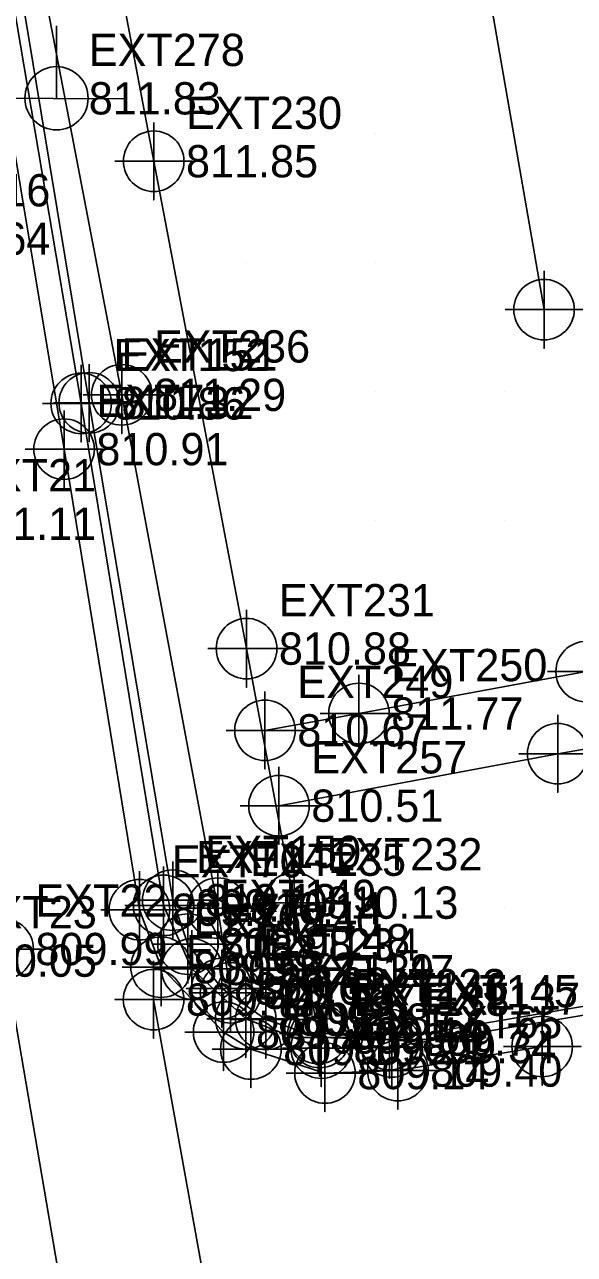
# Model space of a CAD drawing. Extents: x 1762120 to 1766775, y 709485 to 712965.
# Drawn here: x 1763832.9 to 1763875.4, y 712653.2 to 712748.4 of the extents above; entities that cross this region are included whole.
import ezdxf

# ---------------------------------------------------------------- set-up
doc = ezdxf.new("R2010")
doc.units = 0
for name, color, linetype in [('Exist Building', 7, 'Continuous'), ('Exist Building Cogo Point CELL', 7, 'Continuous'), ('Exist DTM Crownline Cogo Elevation', 7, 'Continuous'), ('Exist DTM Crownline Cogo Number', 7, 'Continuous'), ('Exist DTM Drainline', 7, 'Continuous'), ('Exist DTM Drainline Cogo Elevation', 7, 'Continuous'), ('Exist DTM Drainline Cogo Number', 7, 'Continuous'), ('Exist DTM Drainline Cogo Point CELL', 7, 'Continuous'), ('Exist DTM QL2 LIDAR Elevation Point', 7, 'Continuous'), ('Exist Roads Curbs', 7, 'Continuous'), ('Exist Roads Curbs Cogo Elevation', 7, 'Continuous'), ('Exist Roads Curbs Cogo Number', 7, 'Continuous'), ('Exist Roads Curbs Cogo Point CELL', 7, 'Continuous'), ('Exist Roads EOP', 7, 'Continuous'), ('Exist Roads EOP Cogo Elevation', 7, 'Continuous'), ('Exist Roads EOP Cogo Number', 7, 'Continuous'), ('Exist Roads EOP Cogo Point CELL', 7, 'Continuous'), ('Exist Roads EOP Other', 7, 'Continuous'), ('Exist Roads EOP Other Cogo Elevation', 7, 'Continuous'), ('Exist Roads EOP Other Cogo Number', 7, 'Continuous'), ('Exist Roads EOP Other Cogo Point CELL', 7, 'Continuous'), ('Exist Roads EOT', 7, 'Continuous'), ('Exist Roads EOT Cogo Elevation', 7, 'Continuous'), ('Exist Roads EOT Cogo Number', 7, 'Continuous'), ('Exist Roads EOT Cogo Point CELL', 7, 'Continuous'), ('Exist Utilities Power Joint Use Telephone CELL', 7, 'Continuous'), ('Exist Utilities Power Joint Use Telephone Cogo Elevation', 7, 'Continuous'), ('Exist Utilities Power Joint Use Telephone Cogo Number', 7, 'Continuous')]:
    doc.layers.add(name, color=color, linetype=linetype)

msp = doc.modelspace()

# ---------------------------------------------------------------- linework, layer by layer
at = {"layer": 'Exist Building'}
msp.add_line((1763873.081, 712726.353), (1763860.691, 712797.906), dxfattribs=at)
at = {"layer": 'Exist Building Cogo Point CELL'}
msp.add_lwpolyline([(1763873.081, 712729.353), (1763873.081, 712723.353), (1763873.081, 712726.353), (1763876.081, 712726.353), (1763870.081, 712726.353)], dxfattribs=at)
msp.add_circle((1763873.081, 712726.353), 2.344, dxfattribs=at)
at = {"layer": 'Exist DTM Drainline'}
msp.add_lwpolyline([(1763888.176, 712675.965), (1763883.465, 712673.426), (1763879.421, 712672.239), (1763861.295, 712669.219), (1763855.834, 712669.139), (1763849.992, 712671.404), (1763845.815, 712675.27), (1763843.641, 712680.197), (1763837.254, 712719.085), (1763830.877, 712756.626), (1763824.422, 712795.511), (1763818.53, 712833.611)], dxfattribs=at)
at = {"layer": 'Exist DTM Drainline Cogo Point CELL'}
for points in [[(1763837.254, 712722.085), (1763837.254, 712716.085), (1763837.254, 712719.085), (1763840.254, 712719.085), (1763834.254, 712719.085)], [(1763843.641, 712683.197), (1763843.641, 712677.197), (1763843.641, 712680.197), (1763846.641, 712680.197), (1763840.641, 712680.197)], [(1763845.815, 712678.27), (1763845.815, 712672.27), (1763845.815, 712675.27), (1763848.815, 712675.27), (1763842.815, 712675.27)], [(1763849.992, 712674.404), (1763849.992, 712668.404), (1763849.992, 712671.404), (1763852.992, 712671.404), (1763846.992, 712671.404)], [(1763855.834, 712672.139), (1763855.834, 712666.139), (1763855.834, 712669.139), (1763858.834, 712669.139), (1763852.834, 712669.139)], [(1763861.295, 712672.219), (1763861.295, 712666.219), (1763861.295, 712669.219), (1763864.295, 712669.219), (1763858.295, 712669.219)]]:
    msp.add_lwpolyline(points, dxfattribs=at)
for centre in [(1763837.254, 712719.085), (1763843.641, 712680.197), (1763845.815, 712675.27), (1763849.992, 712671.404), (1763861.295, 712669.219), (1763855.834, 712669.139)]:
    msp.add_circle(centre, 2.344, dxfattribs=at)
at = {"layer": 'Exist DTM QL2 LIDAR Elevation Point'}
for p, q in [((1763850, 712740), (1763850, 712740)), ((1763860, 712740), (1763860, 712740)), ((1763850, 712730), (1763850, 712730)), ((1763860, 712730), (1763860, 712730)), ((1763850, 712720), (1763850, 712720)), ((1763860, 712720), (1763860, 712720)), ((1763870, 712720), (1763870, 712720)), ((1763860, 712710), (1763860, 712710)), ((1763870, 712710), (1763870, 712710)), ((1763860, 712700), (1763860, 712700)), ((1763870, 712700), (1763870, 712700)), ((1763860, 712680), (1763860, 712680)), ((1763870, 712680), (1763870, 712680))]:
    msp.add_line(p, q, dxfattribs=at)
at = {"layer": 'Exist Roads Curbs'}
msp.add_lwpolyline([(1763887.913, 712676.609), (1763883.105, 712673.993), (1763879.529, 712672.953), (1763861.13, 712669.797), (1763855.716, 712669.958), (1763851.546, 712671.351), (1763848.135, 712673.751), (1763845.524, 712677.19), (1763844.339, 712680.601), (1763837.881, 712719.135), (1763831.693, 712756.599), (1763825.169, 712795.603), (1763818.676, 712837.176), (1763818.589, 712840.745), (1763820.694, 712846.562), (1763822.71, 712849.767), (1763826.551, 712853.145), (1763830.571, 712855.107), (1763844.339, 712857.64), (1763850.134, 712857.271), (1763855.594, 712854.564), (1763859.316, 712849.842), (1763861.632, 712843.383)], dxfattribs=at)
at = {"layer": 'Exist Roads Curbs Cogo Point CELL'}
for points in [[(1763837.881, 712722.135), (1763837.881, 712716.135), (1763837.881, 712719.135), (1763835.151, 712719.135), (1763840.881, 712719.135)], [(1763844.339, 712683.601), (1763844.339, 712677.601), (1763844.339, 712680.601), (1763841.609, 712680.601), (1763847.339, 712680.601)], [(1763845.524, 712680.19), (1763845.524, 712674.19), (1763845.524, 712677.19), (1763842.794, 712677.19), (1763848.524, 712677.19)], [(1763848.135, 712676.751), (1763848.135, 712670.751), (1763848.135, 712673.751), (1763845.405, 712673.751), (1763851.135, 712673.751)], [(1763851.546, 712674.351), (1763851.546, 712668.351), (1763851.546, 712671.351), (1763848.816, 712671.351), (1763854.546, 712671.351)], [(1763855.716, 712672.958), (1763855.716, 712666.958), (1763855.716, 712669.958), (1763852.986, 712669.958), (1763858.716, 712669.958)], [(1763861.13, 712672.797), (1763861.13, 712666.797), (1763861.13, 712669.797), (1763858.4, 712669.797), (1763864.13, 712669.797)]]:
    msp.add_lwpolyline(points, dxfattribs=at)
for centre in [(1763837.881, 712719.135), (1763844.339, 712680.601), (1763845.524, 712677.19), (1763848.135, 712673.751), (1763851.546, 712671.351), (1763855.716, 712669.958), (1763861.13, 712669.797)]:
    msp.add_circle(centre, 2.344, dxfattribs=at)
at = {"layer": 'Exist Roads EOP'}
msp.add_lwpolyline([(1763872.939, 712669.264), (1763861.771, 712667.397), (1763856.129, 712667.205), (1763850.394, 712669.068), (1763848.283, 712670.385), (1763843.436, 712675.406), (1763841.767, 712679.86), (1763835.931, 712715.544), (1763829.184, 712756.072), (1763822.427, 712796.443), (1763817.324, 712826.974), (1763816.07, 712838.811), (1763818.954, 712848.93), (1763823.982, 712854.424), (1763830.822, 712857.794), (1763839.256, 712859.239)], dxfattribs=at)
at = {"layer": 'Exist Roads EOP Cogo Point CELL'}
for points in [[(1763835.931, 712718.544), (1763835.931, 712712.544), (1763835.931, 712715.544), (1763838.931, 712715.544), (1763832.931, 712715.544)], [(1763841.767, 712682.86), (1763841.767, 712676.86), (1763841.767, 712679.86), (1763844.767, 712679.86), (1763838.767, 712679.86)], [(1763843.436, 712678.406), (1763843.436, 712672.406), (1763843.436, 712675.406), (1763846.436, 712675.406), (1763840.436, 712675.406)], [(1763848.283, 712673.385), (1763848.283, 712667.385), (1763848.283, 712670.385), (1763851.283, 712670.385), (1763845.283, 712670.385)], [(1763850.394, 712672.068), (1763850.394, 712666.068), (1763850.394, 712669.068), (1763853.394, 712669.068), (1763847.394, 712669.068)], [(1763872.939, 712672.264), (1763872.939, 712666.264), (1763872.939, 712669.264), (1763875.939, 712669.264), (1763869.939, 712669.264)], [(1763856.129, 712670.205), (1763856.129, 712664.205), (1763856.129, 712667.205), (1763859.129, 712667.205), (1763853.129, 712667.205)], [(1763861.771, 712670.397), (1763861.771, 712664.397), (1763861.771, 712667.397), (1763864.771, 712667.397), (1763858.771, 712667.397)]]:
    msp.add_lwpolyline(points, dxfattribs=at)
for centre in [(1763835.931, 712715.544), (1763841.767, 712679.86), (1763843.436, 712675.406), (1763848.283, 712670.385), (1763872.939, 712669.264), (1763850.394, 712669.068), (1763861.771, 712667.397), (1763856.129, 712667.205)]:
    msp.add_circle(centre, 2.344, dxfattribs=at)
at = {"layer": 'Exist Roads EOP Other'}
for points in [[(1763823.74, 712850.658), (1763829.272, 712813.477), (1763835.791, 712775.327), (1763842.869, 712737.848), (1763850.058, 712700.088), (1763853.731, 712680.407), (1763855.596, 712670.266)], [(1763848.821, 712673.422), (1763847.825, 712679.985), (1763840.398, 712719.751), (1763833.777, 712754.373), (1763826.475, 712793.95), (1763821.461, 712826.921), (1763819.116, 712842.201)], [(1763851.484, 712693.757), (1763858.758, 712695.065), (1763876.347, 712698.307), (1763886.241, 712700.113), (1763914.739, 712705.328)], [(1763916.286, 712699.606), (1763891.551, 712695.001), (1763874.144, 712691.949), (1763852.567, 712687.92)]]:
    msp.add_lwpolyline(points, dxfattribs=at)
at = {"layer": 'Exist Roads EOP Other Cogo Point CELL'}
for points in [[(1763842.869, 712740.848), (1763842.869, 712734.848), (1763842.869, 712737.848), (1763845.869, 712737.848), (1763839.869, 712737.848)], [(1763840.398, 712722.751), (1763840.398, 712716.751), (1763840.398, 712719.751), (1763843.398, 712719.751), (1763837.398, 712719.751)], [(1763850.058, 712703.088), (1763850.058, 712697.088), (1763850.058, 712700.088), (1763853.058, 712700.088), (1763847.058, 712700.088)], [(1763876.347, 712701.307), (1763876.347, 712695.307), (1763876.347, 712698.307), (1763879.347, 712698.307), (1763873.347, 712698.307)], [(1763858.758, 712698.065), (1763858.758, 712692.065), (1763858.758, 712695.065), (1763861.758, 712695.065), (1763855.758, 712695.065)], [(1763851.484, 712696.757), (1763851.484, 712690.757), (1763851.484, 712693.757), (1763854.484, 712693.757), (1763848.484, 712693.757)], [(1763874.144, 712694.949), (1763874.144, 712688.949), (1763874.144, 712691.949), (1763877.144, 712691.949), (1763871.144, 712691.949)], [(1763852.567, 712690.92), (1763852.567, 712684.92), (1763852.567, 712687.92), (1763855.567, 712687.92), (1763849.567, 712687.92)], [(1763847.825, 712682.985), (1763847.825, 712676.985), (1763847.825, 712679.985), (1763850.825, 712679.985), (1763844.825, 712679.985)], [(1763853.731, 712683.407), (1763853.731, 712677.407), (1763853.731, 712680.407), (1763856.731, 712680.407), (1763850.731, 712680.407)], [(1763848.821, 712676.422), (1763848.821, 712670.422), (1763848.821, 712673.422), (1763851.821, 712673.422), (1763845.821, 712673.422)], [(1763855.596, 712673.266), (1763855.596, 712667.266), (1763855.596, 712670.266), (1763858.596, 712670.266), (1763852.596, 712670.266)]]:
    msp.add_lwpolyline(points, dxfattribs=at)
for centre in [(1763842.869, 712737.848), (1763840.398, 712719.751), (1763850.058, 712700.088), (1763876.347, 712698.307), (1763858.758, 712695.065), (1763851.484, 712693.757), (1763874.144, 712691.949), (1763852.567, 712687.92), (1763847.825, 712679.985), (1763853.731, 712680.407), (1763848.821, 712673.422), (1763855.596, 712670.266)]:
    msp.add_circle(centre, 2.344, dxfattribs=at)
at = {"layer": 'Exist Roads EOT'}
msp.add_line((1763842.863, 712672.898), (1763849.88, 712633.986), dxfattribs=at)
msp.add_lwpolyline([(1763789.832, 712926.884), (1763795.992, 712888.052), (1763800.75, 712859.942), (1763807.254, 712820.955), (1763816.86, 712762.721), (1763822.148, 712731.849), (1763825.695, 712709.767), (1763831.213, 712676.817), (1763837.744, 712638.56), (1763842.2, 712611.183), (1763849.139, 712569.759)], dxfattribs=at)
at = {"layer": 'Exist Roads EOT Cogo Point CELL'}
for points in [[(1763831.213, 712679.817), (1763831.213, 712673.817), (1763831.213, 712676.817), (1763828.213, 712676.817), (1763834.213, 712676.817)], [(1763842.863, 712675.898), (1763842.863, 712669.898), (1763842.863, 712672.898), (1763839.863, 712672.898), (1763845.863, 712672.898)]]:
    msp.add_lwpolyline(points, dxfattribs=at)
for centre in [(1763831.213, 712676.817), (1763842.863, 712672.898)]:
    msp.add_circle(centre, 2.344, dxfattribs=at)
at = {"layer": 'Exist Utilities Power Joint Use Telephone CELL'}
msp.add_line((1763835.346, 712742.723), (1763835.346, 712742.723), dxfattribs=at)
msp.add_lwpolyline([(1763829.409, 712742.723), (1763840.746, 712742.685), (1763835.346, 712742.703), (1763835.346, 712748.348)], dxfattribs=at)
msp.add_circle((1763835.347, 712742.729), 2.45, dxfattribs=at)

# ---------------------------------------------------------------- texts
at = {"layer": 'Exist DTM Crownline Cogo Elevation'}
msp.add_text('810.05', height=2.5, dxfattribs=at).set_placement((1763828.249, 712674.666))
at = {"layer": 'Exist DTM Crownline Cogo Number'}
msp.add_text('EXT23', height=2.5, dxfattribs=at).set_placement((1763828.249, 712678.416))
at = {"layer": 'Exist DTM Drainline Cogo Elevation'}
for s, p in [('810.86', (1763839.754, 712717.835)), ('809.70', (1763846.141, 712678.947)), ('809.52', (1763848.315, 712674.02)), ('809.28', (1763852.492, 712670.154)), ('809.21', (1763858.334, 712667.889)), ('809.34', (1763863.795, 712667.969))]:
    msp.add_text(s, height=2.5, dxfattribs=at).set_placement(p)
at = {"layer": 'Exist DTM Drainline Cogo Number'}
for s, p in [('EXT152', (1763839.754, 712721.585)), ('EXT141', (1763846.141, 712682.697)), ('EXT140', (1763848.315, 712677.77)), ('EXT139', (1763852.492, 712673.904)), ('EXT138', (1763858.334, 712671.639)), ('EXT137', (1763863.795, 712671.719))]:
    msp.add_text(s, height=2.5, dxfattribs=at).set_placement(p)
at = {"layer": 'Exist Roads Curbs Cogo Elevation'}
for s, p in [('811.32', (1763840.381, 712717.885)), ('810.13', (1763846.839, 712679.351)), ('809.98', (1763848.024, 712675.94)), ('809.62', (1763850.635, 712672.501)), ('809.38', (1763854.046, 712670.101)), ('809.50', (1763858.216, 712668.708)), ('809.72', (1763863.63, 712668.547))]:
    msp.add_text(s, height=2.5, dxfattribs=at).set_placement(p)
at = {"layer": 'Exist Roads Curbs Cogo Number'}
for s, p in [('EXT151', (1763840.381, 712721.635)), ('EXT150', (1763846.839, 712683.101)), ('EXT149', (1763848.024, 712679.69)), ('EXT148', (1763850.635, 712676.251)), ('EXT147', (1763854.046, 712673.851)), ('EXT146', (1763858.216, 712672.458)), ('EXT145', (1763863.63, 712672.297))]:
    msp.add_text(s, height=2.5, dxfattribs=at).set_placement(p)
at = {"layer": 'Exist Roads EOP Cogo Elevation'}
for s, p in [('810.91', (1763838.431, 712714.294)), ('809.77', (1763844.267, 712678.61)), ('809.52', (1763845.936, 712674.156)), ('809.20', (1763850.783, 712669.135)), ('809.16', (1763852.894, 712667.818)), ('809.40', (1763864.271, 712666.147)), ('809.14', (1763858.629, 712665.955))]:
    msp.add_text(s, height=2.5, dxfattribs=at).set_placement(p)
at = {"layer": 'Exist Roads EOP Cogo Number'}
for s, p in [('EXT71', (1763838.431, 712718.044)), ('EXT70', (1763844.267, 712682.36)), ('EXT69', (1763845.936, 712677.906)), ('EXT68', (1763850.783, 712672.885)), ('EXT67', (1763852.894, 712671.568)), ('EXT66', (1763858.629, 712669.705)), ('EXT65', (1763864.271, 712669.897))]:
    msp.add_text(s, height=2.5, dxfattribs=at).set_placement(p)
at = {"layer": 'Exist Roads EOP Other Cogo Elevation'}
for s, p in [('811.85', (1763845.369, 712736.598)), ('811.29', (1763842.898, 712718.501)), ('810.88', (1763852.558, 712698.838)), ('811.77', (1763861.258, 712693.815)), ('810.67', (1763853.984, 712692.507)), ('810.51', (1763855.067, 712686.67)), ('810.14', (1763850.325, 712678.735)), ('810.13', (1763856.231, 712679.157)), ('809.58', (1763851.321, 712672.172)), ('809.44', (1763858.096, 712669.016))]:
    msp.add_text(s, height=2.5, dxfattribs=at).set_placement(p)
at = {"layer": 'Exist Roads EOP Other Cogo Number'}
for s, p in [('EXT230', (1763845.369, 712740.348)), ('EXT236', (1763842.898, 712722.251)), ('EXT231', (1763852.558, 712702.588)), ('EXT250', (1763861.258, 712697.565)), ('EXT249', (1763853.984, 712696.257)), ('EXT257', (1763855.067, 712690.42)), ('EXT235', (1763850.325, 712682.485)), ('EXT232', (1763856.231, 712682.907)), ('EXT234', (1763851.321, 712675.922)), ('EXT233', (1763858.096, 712672.766))]:
    msp.add_text(s, height=2.5, dxfattribs=at).set_placement(p)
at = {"layer": 'Exist Roads EOT Cogo Elevation'}
for s, p in [('811.64', (1763824.648, 712730.599)), ('811.11', (1763828.195, 712708.517)), ('809.99', (1763833.713, 712675.567)), ('809.44', (1763845.363, 712671.648))]:
    msp.add_text(s, height=2.5, dxfattribs=at).set_placement(p)
at = {"layer": 'Exist Roads EOT Cogo Number'}
for s, p in [('EXT16', (1763824.648, 712734.349)), ('EXT21', (1763828.195, 712712.267)), ('EXT22', (1763833.713, 712679.317)), ('EXT63', (1763845.363, 712675.398))]:
    msp.add_text(s, height=2.5, dxfattribs=at).set_placement(p)
at = {"layer": 'Exist Utilities Power Joint Use Telephone Cogo Elevation'}
msp.add_text('811.83', height=2.5, dxfattribs=at).set_placement((1763837.846, 712741.473))
at = {"layer": 'Exist Utilities Power Joint Use Telephone Cogo Number'}
msp.add_text('EXT278', height=2.5, dxfattribs=at).set_placement((1763837.846, 712745.223))

doc.saveas('drawing.dxf')
